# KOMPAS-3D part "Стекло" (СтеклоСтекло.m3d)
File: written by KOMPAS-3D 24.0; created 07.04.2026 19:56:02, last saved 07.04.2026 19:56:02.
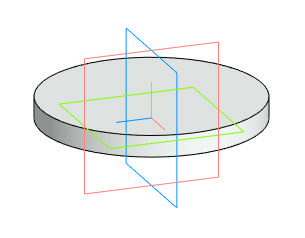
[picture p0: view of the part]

Document properties: Автор: Main; Полное имя файла: D:\DN.ru Аутсерс\Стекло смотровое DN.ru\Исходники\Стекло смотровое DN.ru SG2-34G-F тип В ГОСТ 21836-2021 Ду65 Ру16, углеродистая сталь, фланцевое\СтеклоСтекло.m3d

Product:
- Body: Твердое тело1  | qty 1
- Part/product: Стекло

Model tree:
1. Твердое тело1  (labels: Твердое тело1)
